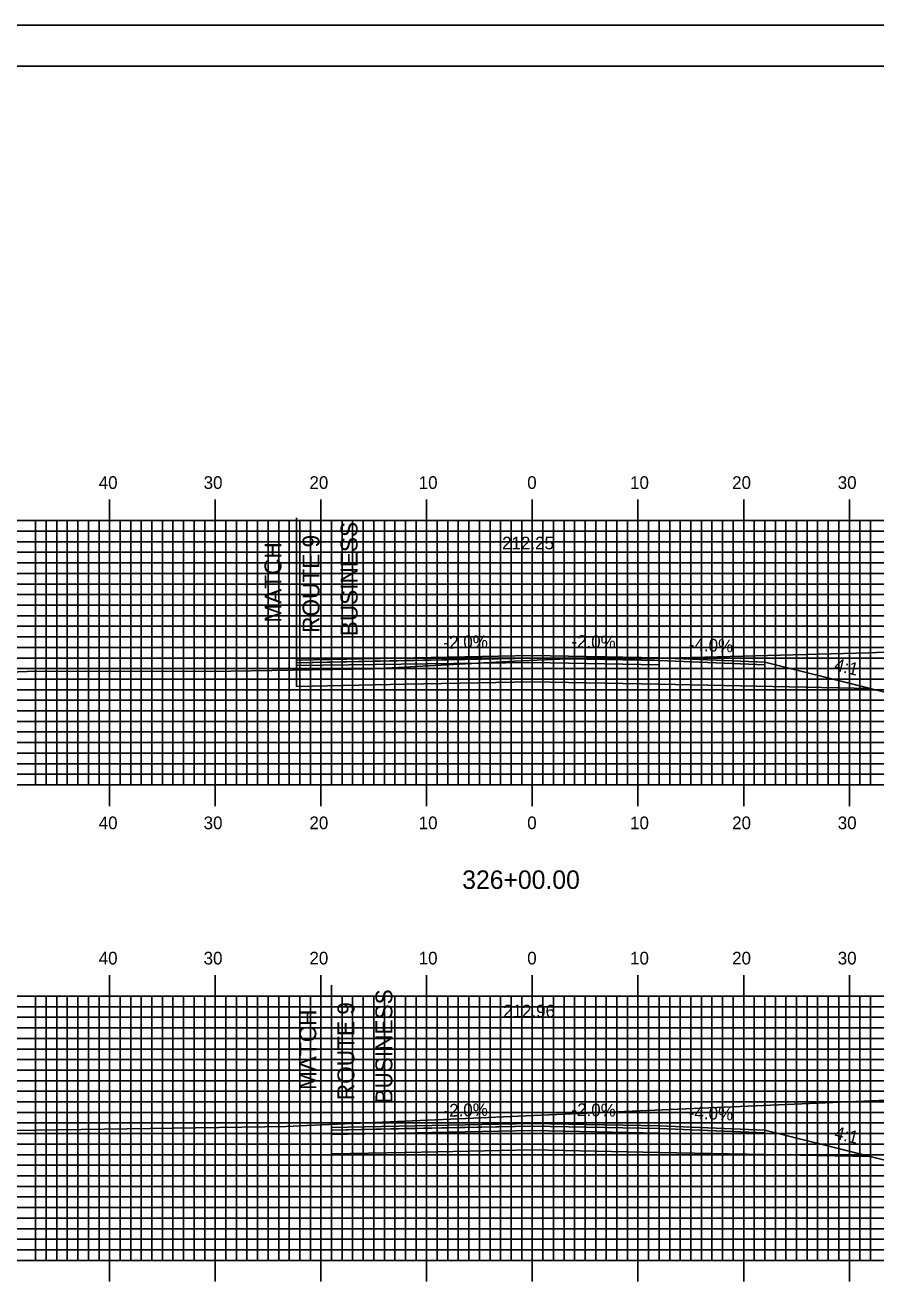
# Model space of a CAD drawing. Extents: x 1821211 to 1821555, y 442591 to 442811.
# Drawn here: x 1821329.2 to 1821409.7, y 442691.2 to 442810.5 of the extents above; entities that cross this region are included whole.
import ezdxf

# ---------------------------------------------------------------- set-up
doc = ezdxf.new("R2010")
doc.units = 0
for name, color, linetype in [('ANNOTATION', 7, 'Continuous'), ('BORDER', 7, 'Continuous'), ('D_Roadway_Centerline', 7, 'Continuous'), ('D_Roadway_Centerline_Text', 7, 'Continuous'), ('D_Roadway_Edge_Shoulder', 7, 'Continuous'), ('D_Roadway_Edge_TW', 7, 'Continuous'), ('D_Roadway_Pavement', 7, 'Continuous'), ('D_Roadway_SlopeLines', 7, 'Continuous'), ('D_Roadway_SubGrade', 7, 'Continuous'), ('H_V ANNOTATION', 7, 'Continuous'), ('MAJOR', 7, 'Continuous'), ('MINOR', 7, 'Continuous'), ('PLOT BOUNDARY', 7, 'Continuous'), ('S_Roadway_Centerline', 7, 'Continuous')]:
    doc.layers.add(name, color=color, linetype=linetype)

msp = doc.modelspace()

# ---------------------------------------------------------------- linework, layer by layer
at = {"layer": 'ANNOTATION'}
for p, q in [((1821354.93, 442747.97), (1821354.93, 442751.99)), ((1821354.93, 442750.22), (1821354.93, 442749.97)), ((1821358.23, 442703.75), (1821358.23, 442707.73)), ((1821358.23, 442705.58), (1821358.23, 442703.75))]:
    msp.add_line(p, q, dxfattribs=at)
at = {"layer": 'BORDER'}
msp.add_lwpolyline([(1821227.63, 442596.67), (1821547.63, 442596.67), (1821547.63, 442806.67), (1821227.63, 442806.67)], close=True, dxfattribs=at)
at = {"layer": 'D_Roadway_Edge_Shoulder'}
for points in [[(1821389.23, 442750.68), (1821399.23, 442750.28), (1821399.23, 442750.03), (1821389.23, 442750.43)], [(1821389.23, 442706.39), (1821399.23, 442705.99), (1821399.23, 442705.74), (1821389.23, 442706.14)]]:
    msp.add_lwpolyline(points, close=True, dxfattribs=at)
at = {"layer": 'D_Roadway_Edge_TW'}
for points in [[(1821354.93, 442750.22), (1821354.93, 442750.47), (1821377.23, 442750.92), (1821389.23, 442750.68), (1821389.23, 442750.43), (1821377.23, 442750.67)], [(1821358.23, 442706), (1821358.23, 442706.25), (1821377.23, 442706.63), (1821389.23, 442706.39), (1821389.23, 442706.14), (1821377.23, 442706.38)]]:
    msp.add_lwpolyline(points, close=True, dxfattribs=at)
at = {"layer": 'D_Roadway_Pavement'}
for points in [[(1821354.93, 442749.97), (1821354.93, 442750.22), (1821377.23, 442750.67), (1821389.23, 442750.43), (1821389.23, 442750.01), (1821377.23, 442750.25)], [(1821358.23, 442705.58), (1821358.23, 442706), (1821377.23, 442706.38), (1821389.23, 442706.14), (1821389.23, 442705.72), (1821377.23, 442705.96)]]:
    msp.add_lwpolyline(points, close=True, dxfattribs=at)
at = {"layer": 'D_Roadway_SlopeLines'}
for points in [[(1821399.23, 442750.28), (1821413.23, 442746.78)], [(1821399.23, 442705.99), (1821413.23, 442702.49)]]:
    msp.add_lwpolyline(points, dxfattribs=at)
at = {"layer": 'D_Roadway_SubGrade'}
for p, q in [((1821354.93, 442763.93), (1821354.93, 442747.97)), ((1821358.23, 442719.7), (1821358.23, 442703.75))]:
    msp.add_line(p, q, dxfattribs=at)
msp.add_lwpolyline([(1821365.23, 442748.18), (1821354.93, 442747.97), (1821354.93, 442750.22), (1821354.93, 442749.78), (1821354.93, 442749.81), (1821354.93, 442750.22), (1821365.23, 442750.43), (1821377.23, 442750.67), (1821389.23, 442750.43), (1821399.23, 442750.03), (1821399.23, 442750.28), (1821409.23, 442747.78), (1821389.23, 442748.18), (1821377.23, 442748.42)], close=True, dxfattribs=at)
msp.add_lwpolyline([(1821358.23, 442706), (1821365.23, 442706.14), (1821377.23, 442706.38), (1821389.23, 442706.14), (1821399.23, 442705.74), (1821399.23, 442705.99), (1821409.23, 442703.49), (1821389.23, 442703.89), (1821377.23, 442704.13), (1821365.23, 442703.89), (1821358.23, 442703.75)], dxfattribs=at)
at = {"layer": 'MAJOR'}
for p, q in [((1821337.23, 442765.67), (1821337.23, 442763.67)), ((1821347.23, 442765.67), (1821347.23, 442763.67)), ((1821357.23, 442765.67), (1821357.23, 442763.67)), ((1821367.23, 442765.67), (1821367.23, 442763.67)), ((1821377.23, 442765.67), (1821377.23, 442763.67)), ((1821387.23, 442765.67), (1821387.23, 442763.67)), ((1821397.23, 442765.67), (1821397.23, 442763.67)), ((1821407.23, 442765.67), (1821407.23, 442763.67)), ((1821237.23, 442763.67), (1821517.23, 442763.67)), ((1821237.23, 442763.67), (1821517.23, 442763.67)), ((1821337.23, 442738.67), (1821337.23, 442763.67)), ((1821347.23, 442738.67), (1821347.23, 442763.67)), ((1821357.23, 442738.67), (1821357.23, 442763.67)), ((1821367.23, 442738.67), (1821367.23, 442763.67)), ((1821377.23, 442738.67), (1821377.23, 442763.67)), ((1821387.23, 442738.67), (1821387.23, 442763.67)), ((1821397.23, 442738.67), (1821397.23, 442763.67)), ((1821407.23, 442738.67), (1821407.23, 442763.67)), ((1821237.23, 442758.67), (1821517.23, 442758.67)), ((1821237.23, 442753.67), (1821517.23, 442753.67)), ((1821237.23, 442748.67), (1821517.23, 442748.67)), ((1821237.23, 442743.67), (1821517.23, 442743.67)), ((1821237.23, 442738.67), (1821517.23, 442738.67)), ((1821237.23, 442738.67), (1821517.23, 442738.67)), ((1821337.23, 442736.66), (1821337.23, 442738.67)), ((1821347.23, 442736.66), (1821347.23, 442738.67)), ((1821357.23, 442736.66), (1821357.23, 442738.67)), ((1821367.23, 442736.66), (1821367.23, 442738.67)), ((1821377.23, 442736.66), (1821377.23, 442738.67)), ((1821387.23, 442736.66), (1821387.23, 442738.67)), ((1821397.23, 442736.66), (1821397.23, 442738.67)), ((1821407.23, 442736.66), (1821407.23, 442738.67)), ((1821337.23, 442720.67), (1821337.23, 442718.67)), ((1821347.23, 442720.67), (1821347.23, 442718.67)), ((1821357.23, 442720.67), (1821357.23, 442718.67)), ((1821367.23, 442720.67), (1821367.23, 442718.67)), ((1821377.23, 442720.67), (1821377.23, 442718.67)), ((1821387.23, 442720.67), (1821387.23, 442718.67)), ((1821397.23, 442720.67), (1821397.23, 442718.67)), ((1821407.23, 442720.67), (1821407.23, 442718.67)), ((1821237.23, 442718.67), (1821517.23, 442718.67)), ((1821237.23, 442718.67), (1821517.23, 442718.67)), ((1821337.23, 442693.67), (1821337.23, 442718.67)), ((1821347.23, 442693.67), (1821347.23, 442718.67)), ((1821357.23, 442693.67), (1821357.23, 442718.67)), ((1821367.23, 442693.67), (1821367.23, 442718.67)), ((1821377.23, 442693.67), (1821377.23, 442718.67)), ((1821387.23, 442693.67), (1821387.23, 442718.67)), ((1821397.23, 442693.67), (1821397.23, 442718.67)), ((1821407.23, 442693.67), (1821407.23, 442718.67)), ((1821237.23, 442713.67), (1821517.23, 442713.67)), ((1821237.23, 442708.67), (1821517.23, 442708.67)), ((1821237.23, 442703.67), (1821517.23, 442703.67)), ((1821237.23, 442698.67), (1821517.23, 442698.67)), ((1821237.23, 442693.67), (1821517.23, 442693.67)), ((1821237.23, 442693.67), (1821517.23, 442693.67)), ((1821337.23, 442691.66), (1821337.23, 442693.67)), ((1821347.23, 442691.66), (1821347.23, 442693.67)), ((1821357.23, 442691.66), (1821357.23, 442693.67)), ((1821367.23, 442691.66), (1821367.23, 442693.67)), ((1821377.23, 442691.66), (1821377.23, 442693.67)), ((1821387.23, 442691.66), (1821387.23, 442693.67)), ((1821397.23, 442691.66), (1821397.23, 442693.67)), ((1821407.23, 442691.66), (1821407.23, 442693.67))]:
    msp.add_line(p, q, dxfattribs=at)
at = {"layer": 'MINOR'}
for p, q in [((1821330.23, 442738.67), (1821330.23, 442763.67)), ((1821331.23, 442738.67), (1821331.23, 442763.67)), ((1821332.23, 442738.67), (1821332.23, 442763.67)), ((1821333.23, 442738.67), (1821333.23, 442763.67)), ((1821334.23, 442738.67), (1821334.23, 442763.67)), ((1821335.23, 442738.67), (1821335.23, 442763.67)), ((1821336.23, 442738.67), (1821336.23, 442763.67)), ((1821338.23, 442738.67), (1821338.23, 442763.67)), ((1821339.23, 442738.67), (1821339.23, 442763.67)), ((1821340.23, 442738.67), (1821340.23, 442763.67)), ((1821341.23, 442738.67), (1821341.23, 442763.67)), ((1821342.23, 442738.67), (1821342.23, 442763.67)), ((1821343.23, 442738.67), (1821343.23, 442763.67)), ((1821344.23, 442738.67), (1821344.23, 442763.67)), ((1821345.23, 442738.67), (1821345.23, 442763.67)), ((1821346.23, 442738.67), (1821346.23, 442763.67)), ((1821348.23, 442738.67), (1821348.23, 442763.67)), ((1821349.23, 442738.67), (1821349.23, 442763.67)), ((1821350.23, 442738.67), (1821350.23, 442763.67)), ((1821351.23, 442738.67), (1821351.23, 442763.67)), ((1821352.23, 442738.67), (1821352.23, 442763.67)), ((1821353.23, 442738.67), (1821353.23, 442763.67)), ((1821354.23, 442738.67), (1821354.23, 442763.67)), ((1821355.23, 442738.67), (1821355.23, 442763.67)), ((1821356.23, 442738.67), (1821356.23, 442763.67)), ((1821358.23, 442738.67), (1821358.23, 442763.67)), ((1821359.23, 442738.67), (1821359.23, 442763.67)), ((1821360.23, 442738.67), (1821360.23, 442763.67)), ((1821361.23, 442738.67), (1821361.23, 442763.67)), ((1821362.23, 442738.67), (1821362.23, 442763.67)), ((1821363.23, 442738.67), (1821363.23, 442763.67)), ((1821364.23, 442738.67), (1821364.23, 442763.67)), ((1821365.23, 442738.67), (1821365.23, 442763.67)), ((1821366.23, 442738.67), (1821366.23, 442763.67)), ((1821368.23, 442738.67), (1821368.23, 442763.67)), ((1821369.23, 442738.67), (1821369.23, 442763.67)), ((1821370.23, 442738.67), (1821370.23, 442763.67)), ((1821371.23, 442738.67), (1821371.23, 442763.67)), ((1821372.23, 442738.67), (1821372.23, 442763.67)), ((1821373.23, 442738.67), (1821373.23, 442763.67)), ((1821374.23, 442738.67), (1821374.23, 442763.67)), ((1821375.23, 442738.67), (1821375.23, 442763.67)), ((1821376.23, 442738.67), (1821376.23, 442763.67)), ((1821378.23, 442738.67), (1821378.23, 442763.67)), ((1821379.23, 442738.67), (1821379.23, 442763.67)), ((1821380.23, 442738.67), (1821380.23, 442763.67)), ((1821381.23, 442738.67), (1821381.23, 442763.67)), ((1821382.23, 442738.67), (1821382.23, 442763.67)), ((1821383.23, 442738.67), (1821383.23, 442763.67)), ((1821384.23, 442738.67), (1821384.23, 442763.67)), ((1821385.23, 442738.67), (1821385.23, 442763.67)), ((1821386.23, 442738.67), (1821386.23, 442763.67)), ((1821388.23, 442738.67), (1821388.23, 442763.67)), ((1821389.23, 442738.67), (1821389.23, 442763.67)), ((1821390.23, 442738.67), (1821390.23, 442763.67)), ((1821391.23, 442738.67), (1821391.23, 442763.67)), ((1821392.23, 442738.67), (1821392.23, 442763.67)), ((1821393.23, 442738.67), (1821393.23, 442763.67)), ((1821394.23, 442738.67), (1821394.23, 442763.67)), ((1821395.23, 442738.67), (1821395.23, 442763.67)), ((1821396.23, 442738.67), (1821396.23, 442763.67)), ((1821398.23, 442738.67), (1821398.23, 442763.67)), ((1821399.23, 442738.67), (1821399.23, 442763.67)), ((1821400.23, 442738.67), (1821400.23, 442763.67)), ((1821401.23, 442738.67), (1821401.23, 442763.67)), ((1821402.23, 442738.67), (1821402.23, 442763.67)), ((1821403.23, 442738.67), (1821403.23, 442763.67)), ((1821404.23, 442738.67), (1821404.23, 442763.67)), ((1821405.23, 442738.67), (1821405.23, 442763.67)), ((1821406.23, 442738.67), (1821406.23, 442763.67)), ((1821408.23, 442738.67), (1821408.23, 442763.67)), ((1821409.23, 442738.67), (1821409.23, 442763.67)), ((1821237.23, 442762.67), (1821517.23, 442762.67)), ((1821237.23, 442761.67), (1821517.23, 442761.67)), ((1821237.23, 442760.67), (1821517.23, 442760.67)), ((1821237.23, 442759.67), (1821517.23, 442759.67)), ((1821237.23, 442757.67), (1821517.23, 442757.67)), ((1821237.23, 442756.67), (1821517.23, 442756.67)), ((1821237.23, 442755.67), (1821517.23, 442755.67)), ((1821237.23, 442754.67), (1821517.23, 442754.67)), ((1821237.23, 442752.67), (1821517.23, 442752.67)), ((1821237.23, 442751.67), (1821517.23, 442751.67)), ((1821237.23, 442750.67), (1821517.23, 442750.67)), ((1821237.23, 442749.67), (1821517.23, 442749.67)), ((1821237.23, 442747.67), (1821517.23, 442747.67)), ((1821237.23, 442746.67), (1821517.23, 442746.67)), ((1821237.23, 442745.67), (1821517.23, 442745.67)), ((1821237.23, 442744.67), (1821517.23, 442744.67)), ((1821237.23, 442742.67), (1821517.23, 442742.67)), ((1821237.23, 442741.67), (1821517.23, 442741.67)), ((1821237.23, 442740.67), (1821517.23, 442740.67)), ((1821237.23, 442739.67), (1821517.23, 442739.67)), ((1821330.23, 442693.67), (1821330.23, 442718.67)), ((1821331.23, 442693.67), (1821331.23, 442718.67)), ((1821332.23, 442693.67), (1821332.23, 442718.67)), ((1821333.23, 442693.67), (1821333.23, 442718.67)), ((1821334.23, 442693.67), (1821334.23, 442718.67)), ((1821335.23, 442693.67), (1821335.23, 442718.67)), ((1821336.23, 442693.67), (1821336.23, 442718.67)), ((1821338.23, 442693.67), (1821338.23, 442718.67)), ((1821339.23, 442693.67), (1821339.23, 442718.67)), ((1821340.23, 442693.67), (1821340.23, 442718.67)), ((1821341.23, 442693.67), (1821341.23, 442718.67)), ((1821342.23, 442693.67), (1821342.23, 442718.67)), ((1821343.23, 442693.67), (1821343.23, 442718.67)), ((1821344.23, 442693.67), (1821344.23, 442718.67)), ((1821345.23, 442693.67), (1821345.23, 442718.67)), ((1821346.23, 442693.67), (1821346.23, 442718.67)), ((1821348.23, 442693.67), (1821348.23, 442718.67)), ((1821349.23, 442693.67), (1821349.23, 442718.67)), ((1821350.23, 442693.67), (1821350.23, 442718.67)), ((1821351.23, 442693.67), (1821351.23, 442718.67)), ((1821352.23, 442693.67), (1821352.23, 442718.67)), ((1821353.23, 442693.67), (1821353.23, 442718.67)), ((1821354.23, 442693.67), (1821354.23, 442718.67)), ((1821355.23, 442693.67), (1821355.23, 442718.67)), ((1821356.23, 442693.67), (1821356.23, 442718.67)), ((1821358.23, 442693.67), (1821358.23, 442718.67)), ((1821359.23, 442693.67), (1821359.23, 442718.67)), ((1821360.23, 442693.67), (1821360.23, 442718.67)), ((1821361.23, 442693.67), (1821361.23, 442718.67)), ((1821362.23, 442693.67), (1821362.23, 442718.67)), ((1821363.23, 442693.67), (1821363.23, 442718.67)), ((1821364.23, 442693.67), (1821364.23, 442718.67)), ((1821365.23, 442693.67), (1821365.23, 442718.67)), ((1821366.23, 442693.67), (1821366.23, 442718.67)), ((1821368.23, 442693.67), (1821368.23, 442718.67)), ((1821369.23, 442693.67), (1821369.23, 442718.67)), ((1821370.23, 442693.67), (1821370.23, 442718.67)), ((1821371.23, 442693.67), (1821371.23, 442718.67)), ((1821372.23, 442693.67), (1821372.23, 442718.67)), ((1821373.23, 442693.67), (1821373.23, 442718.67)), ((1821374.23, 442693.67), (1821374.23, 442718.67)), ((1821375.23, 442693.67), (1821375.23, 442718.67)), ((1821376.23, 442693.67), (1821376.23, 442718.67)), ((1821378.23, 442693.67), (1821378.23, 442718.67)), ((1821379.23, 442693.67), (1821379.23, 442718.67)), ((1821380.23, 442693.67), (1821380.23, 442718.67)), ((1821381.23, 442693.67), (1821381.23, 442718.67)), ((1821382.23, 442693.67), (1821382.23, 442718.67)), ((1821383.23, 442693.67), (1821383.23, 442718.67)), ((1821384.23, 442693.67), (1821384.23, 442718.67)), ((1821385.23, 442693.67), (1821385.23, 442718.67)), ((1821386.23, 442693.67), (1821386.23, 442718.67)), ((1821388.23, 442693.67), (1821388.23, 442718.67)), ((1821389.23, 442693.67), (1821389.23, 442718.67)), ((1821390.23, 442693.67), (1821390.23, 442718.67)), ((1821391.23, 442693.67), (1821391.23, 442718.67)), ((1821392.23, 442693.67), (1821392.23, 442718.67)), ((1821393.23, 442693.67), (1821393.23, 442718.67)), ((1821394.23, 442693.67), (1821394.23, 442718.67)), ((1821395.23, 442693.67), (1821395.23, 442718.67)), ((1821396.23, 442693.67), (1821396.23, 442718.67)), ((1821398.23, 442693.67), (1821398.23, 442718.67)), ((1821399.23, 442693.67), (1821399.23, 442718.67)), ((1821400.23, 442693.67), (1821400.23, 442718.67)), ((1821401.23, 442693.67), (1821401.23, 442718.67)), ((1821402.23, 442693.67), (1821402.23, 442718.67)), ((1821403.23, 442693.67), (1821403.23, 442718.67)), ((1821404.23, 442693.67), (1821404.23, 442718.67)), ((1821405.23, 442693.67), (1821405.23, 442718.67)), ((1821406.23, 442693.67), (1821406.23, 442718.67)), ((1821408.23, 442693.67), (1821408.23, 442718.67)), ((1821409.23, 442693.67), (1821409.23, 442718.67)), ((1821237.23, 442717.67), (1821517.23, 442717.67)), ((1821237.23, 442716.67), (1821517.23, 442716.67)), ((1821237.23, 442715.67), (1821517.23, 442715.67)), ((1821237.23, 442714.67), (1821517.23, 442714.67)), ((1821237.23, 442712.67), (1821517.23, 442712.67)), ((1821237.23, 442711.67), (1821517.23, 442711.67)), ((1821237.23, 442710.67), (1821517.23, 442710.67)), ((1821237.23, 442709.67), (1821517.23, 442709.67)), ((1821237.23, 442707.67), (1821517.23, 442707.67)), ((1821237.23, 442706.67), (1821517.23, 442706.67)), ((1821237.23, 442705.67), (1821517.23, 442705.67)), ((1821237.23, 442704.67), (1821517.23, 442704.67)), ((1821237.23, 442702.67), (1821517.23, 442702.67)), ((1821237.23, 442701.67), (1821517.23, 442701.67)), ((1821237.23, 442700.67), (1821517.23, 442700.67)), ((1821237.23, 442699.67), (1821517.23, 442699.67)), ((1821237.23, 442697.67), (1821517.23, 442697.67)), ((1821237.23, 442696.67), (1821517.23, 442696.67)), ((1821237.23, 442695.67), (1821517.23, 442695.67)), ((1821237.23, 442694.67), (1821517.23, 442694.67))]:
    msp.add_line(p, q, dxfattribs=at)
at = {"layer": 'PLOT BOUNDARY'}
msp.add_lwpolyline([(1821211.44, 442590.55), (1821551.44, 442590.55), (1821551.44, 442810.55), (1821211.44, 442810.55)], close=True, dxfattribs=at)
at = {"layer": 'S_Roadway_Centerline'}
for points in [[(1821325.17, 442749.23), (1821329.44, 442749.38), (1821340.71, 442749.42), (1821346.79, 442749.38), (1821362.22, 442749.65), (1821375.53, 442750.38), (1821379.82, 442750.56), (1821388.78, 442750.62), (1821409.08, 442751.15), (1821423.03, 442751.75), (1821426.49, 442751.84), (1821437.52, 442752.03), (1821440.35, 442752.09), (1821460.04, 442752.79), (1821486.75, 442753.64), (1821493.96, 442753.73), (1821498.54, 442753.82), (1821510.55, 442754.43), (1821517.23, 442754.51)], [(1821237.23, 442703.27), (1821237.53, 442703.28), (1821264.33, 442703.79), (1821303.65, 442705.19), (1821311.23, 442705.53), (1821321.49, 442705.86), (1821351.91, 442706.32), (1821353.94, 442706.35), (1821354.59, 442706.37), (1821355.88, 442706.42), (1821388.83, 442707.87), (1821420.29, 442709.25), (1821422.31, 442709.32), (1821426.24, 442709.4), (1821439.35, 442709.51), (1821465.23, 442709.52), (1821471.24, 442709.51), (1821476.19, 442709.63), (1821481.91, 442709.95), (1821490.45, 442710.34), (1821494.15, 442710.38), (1821514.65, 442710.89), (1821517.23, 442710.91)]]:
    msp.add_lwpolyline(points, dxfattribs=at)

# ---------------------------------------------------------------- texts
at = {"layer": 'ANNOTATION'}
for s, height, rotation, p in [('BUSINESS', 1.6, 90, (1821360.69, 442752.73)), ('ROUTE 9', 1.6, 90, (1821357.09, 442753.05)), ('MATCH', 1.6, 90, (1821353.49, 442754.02)), ('-2.0%', 1.2, 1.1458, (1821368.84, 442751.55)), ('-2.0%', 1.2, 358.8542, (1821380.92, 442751.65)), ('-4.0%', 1.2, 357.7094, (1821392.02, 442751.37)), ('4:1', 1.2, 345.9638, (1821405.74, 442749.52)), ('BUSINESS', 1.6, 90, (1821363.99, 442708.5)), ('MATCH', 1.6, 90, (1821356.79, 442709.79)), ('ROUTE 9', 1.6, 90, (1821360.39, 442708.83)), ('-2.0%', 1.2, 1.1458, (1821368.84, 442707.26)), ('-2.0%', 1.2, 358.8542, (1821380.92, 442707.35)), ('-4.0%', 1.2, 357.7094, (1821392.02, 442707.08)), ('4:1', 1.2, 345.9638, (1821405.74, 442705.22))]:
    msp.add_text(s, height=height, rotation=rotation, dxfattribs=at).set_placement(p)
at = {"layer": 'D_Roadway_Centerline'}
for s, p in [('C', (1821377.22, 442750.92)), ('L', (1821377.23, 442750.91)), ('C', (1821377.22, 442706.63)), ('L', (1821377.23, 442706.62))]:
    msp.add_text(s, height=0.0146, dxfattribs=at).set_placement(p)
at = {"layer": 'D_Roadway_Centerline_Text'}
for s, p in [('212.25', (1821374.37, 442760.95)), ('212.96', (1821374.47, 442716.66))]:
    msp.add_text(s, height=1.2, dxfattribs=at).set_placement(p)
at = {"layer": 'H_V ANNOTATION'}
for s, height, p in [('40', 1.2, (1821336.2, 442766.67)), ('30', 1.2, (1821346.13, 442766.67)), ('20', 1.2, (1821356.14, 442766.67)), ('10', 1.2, (1821366.48, 442766.67)), ('0', 1.2, (1821376.75, 442766.67)), ('10', 1.2, (1821386.48, 442766.67)), ('20', 1.2, (1821396.14, 442766.67)), ('30', 1.2, (1821406.13, 442766.67)), ('40', 1.2, (1821336.2, 442734.47)), ('30', 1.2, (1821346.13, 442734.47)), ('20', 1.2, (1821356.14, 442734.47)), ('10', 1.2, (1821366.48, 442734.47)), ('0', 1.2, (1821376.75, 442734.47)), ('10', 1.2, (1821386.48, 442734.47)), ('20', 1.2, (1821396.14, 442734.47)), ('30', 1.2, (1821406.13, 442734.47)), ('326+00.00', 1.75, (1821370.6, 442728.82)), ('40', 1.2, (1821336.2, 442721.67)), ('30', 1.2, (1821346.13, 442721.67)), ('20', 1.2, (1821356.14, 442721.67)), ('10', 1.2, (1821366.48, 442721.67)), ('0', 1.2, (1821376.75, 442721.67)), ('10', 1.2, (1821386.48, 442721.67)), ('20', 1.2, (1821396.14, 442721.67)), ('30', 1.2, (1821406.13, 442721.67))]:
    msp.add_text(s, height=height, dxfattribs=at).set_placement(p)

doc.saveas('drawing.dxf')
